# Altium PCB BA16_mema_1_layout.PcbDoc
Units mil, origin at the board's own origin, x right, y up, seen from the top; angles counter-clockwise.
Board outline 1653.54 x 2755.91 mil, 2 copper layers (Top Layer, Bottom Layer); 44 components, 23 nets, 138 pads, 0 vias.
Unrouted connection lines stored in the file: 87.
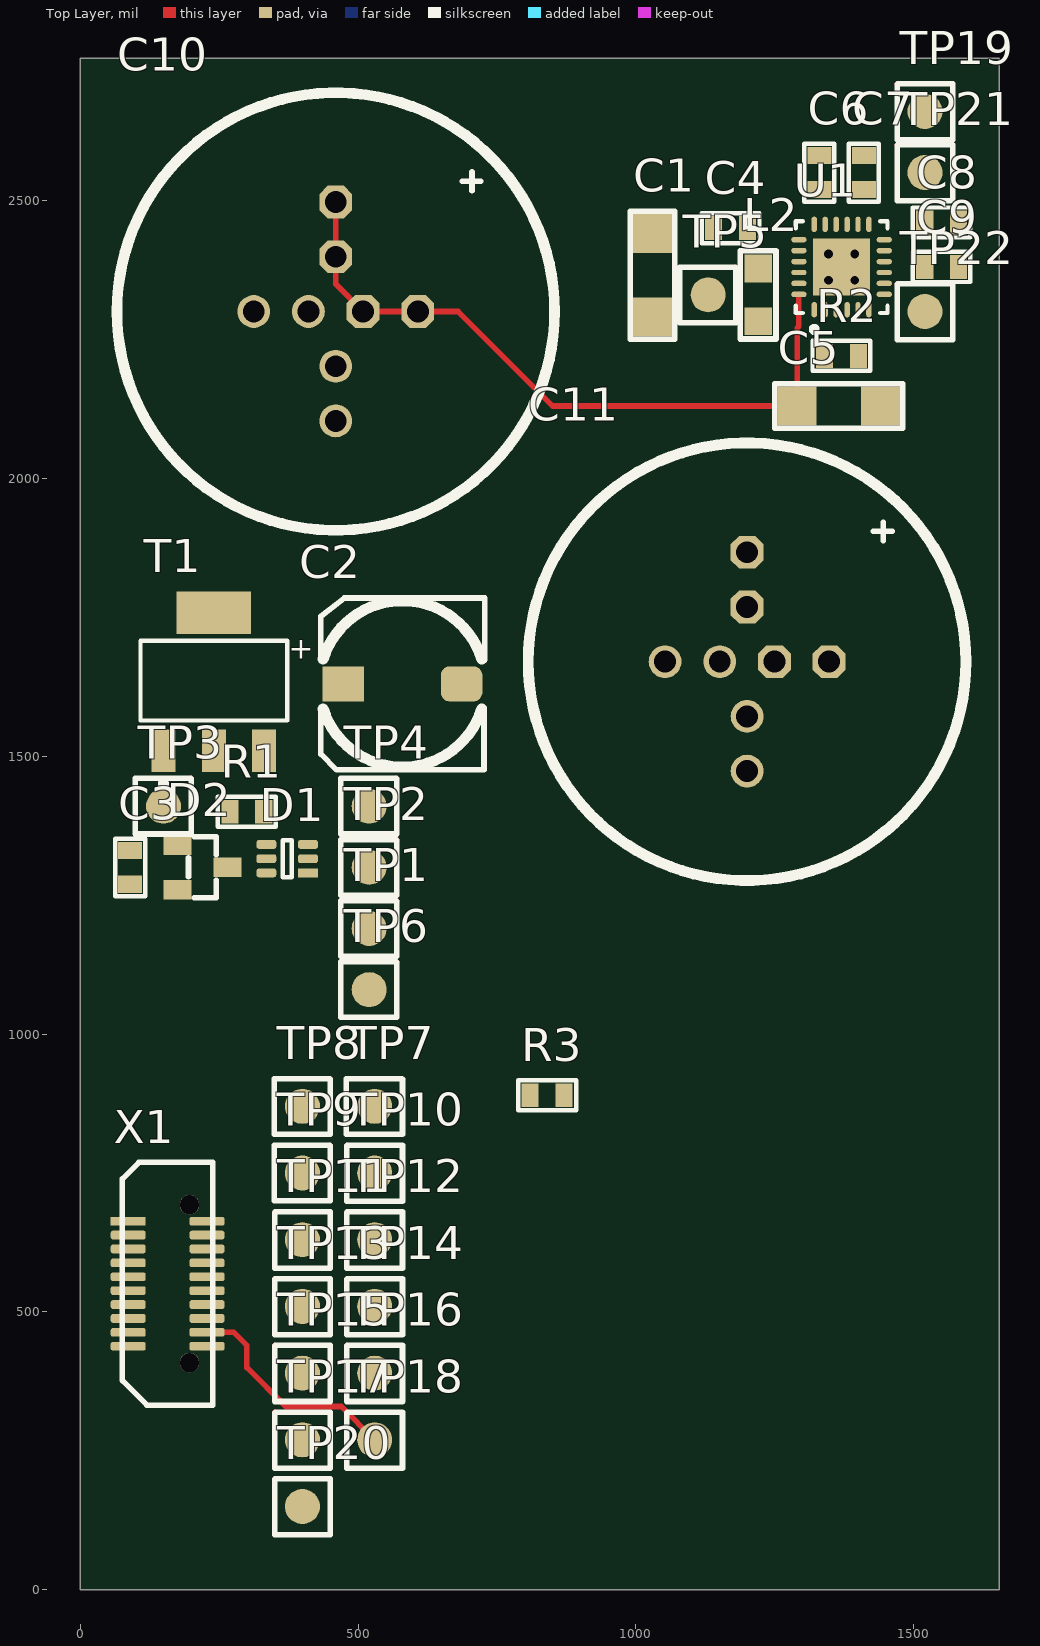
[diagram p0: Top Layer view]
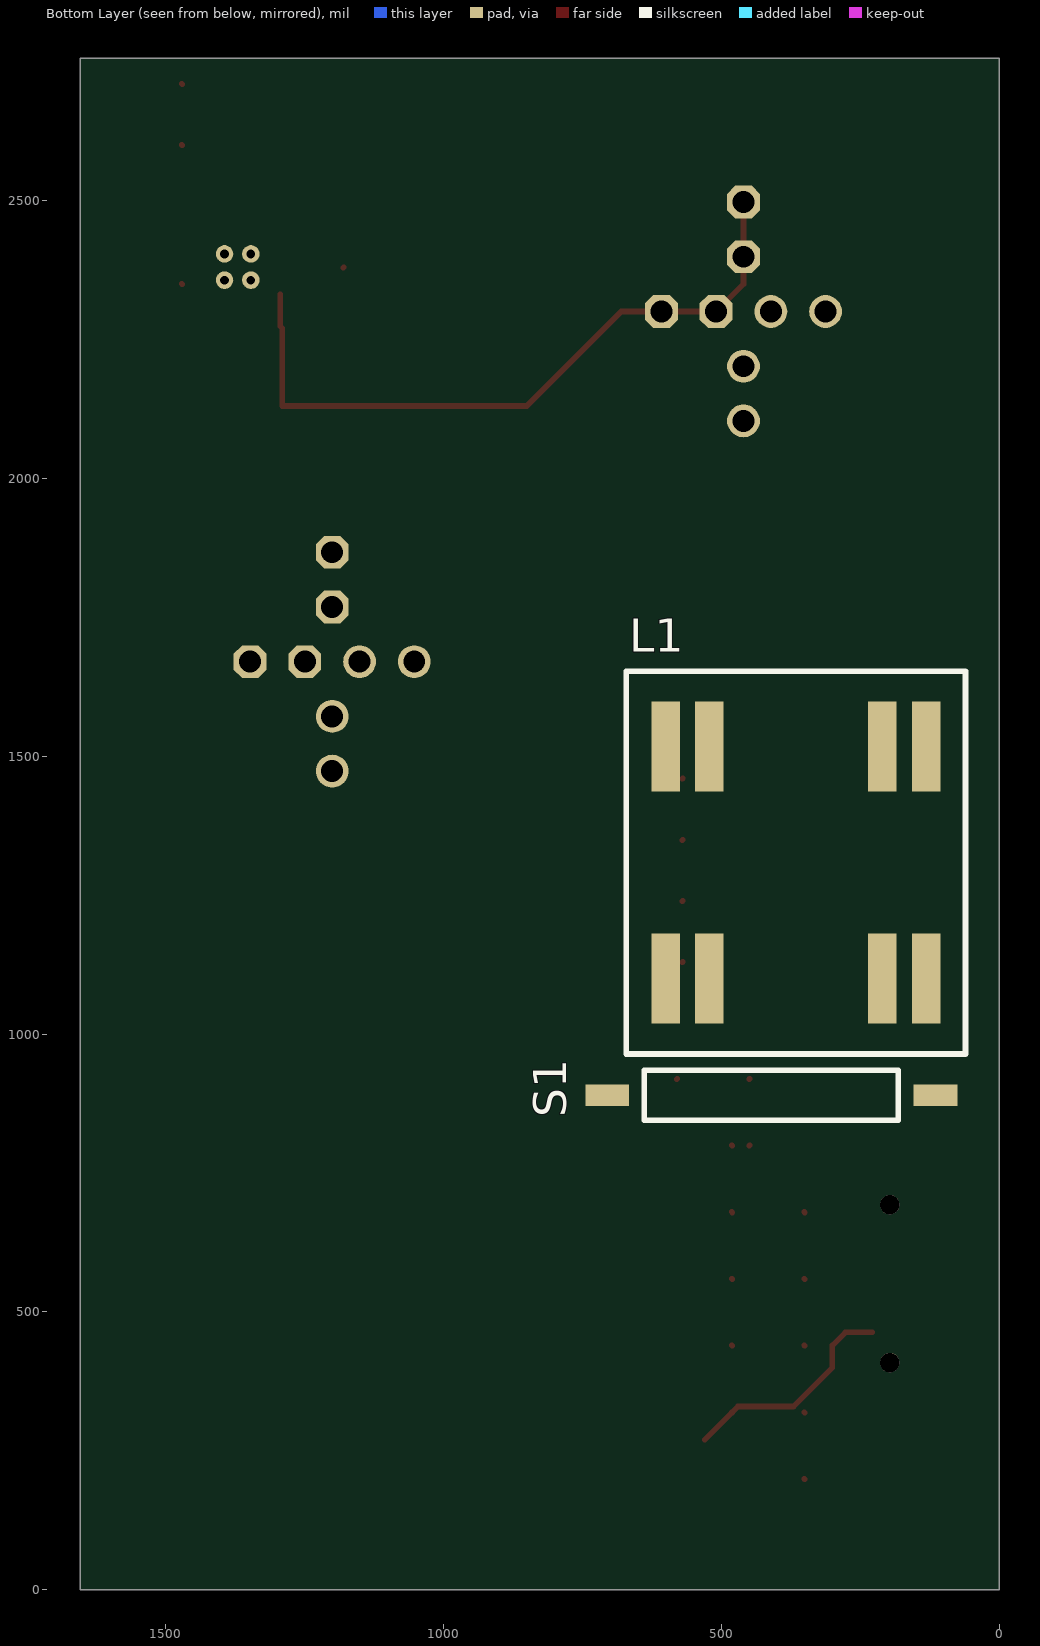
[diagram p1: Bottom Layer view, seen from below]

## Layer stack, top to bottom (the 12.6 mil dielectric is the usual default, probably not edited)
Top Solder: solder mask 0.4, Solder Resist, Dk 3.5
Top Layer: signal copper 1.4
Dielectric 1: dielectric 12.6, FR-4, Dk 4.8
Bottom Layer: signal copper 1.4
Bottom Solder: solder mask 0.4, Solder Resist, Dk 3.5

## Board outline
0,0 0,2755.91 1653.54,2755.91 1653.54,0

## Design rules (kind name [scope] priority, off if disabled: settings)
Clearance [All] p1: gap=10
PolygonConnect [All] p1: connectstyle=Relief reliefconductorwidth=10 reliefentries=4 polygonreliefangle="90 Angle" airgapwidth=10
RoutingVias [All] p1: holewidth=28 width=50 viastyle="Through Hole" minholewidth=28 minwidth=50 maxholewidth=28 maxwidth=50
SolderMaskExpansion [All] p1: expansion=4
Width [All] p1: maxlimit=10 minlimit=10 preferedwidth=10
30 further rules are at their usual default settings.

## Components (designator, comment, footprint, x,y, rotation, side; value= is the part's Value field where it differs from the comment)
C1 "Cap" "CHIP 1206" 1030,2290 r90 top
C2 "47uF 25V" "ELKO SMD-C 6.3x6.3" 580,1630 r0 top
C3 "1nF" "CHIP 0603" 90,1300 r90 top
C4 "Cap" "CHIP 0603" 1170,2450 r180 top
C5 "Cap" "CHIP 1206" 1290,2130 r0 top
C6 "Cap" "CHIP 0603" 1330,2550 r90 top
C7 "Cap" "CHIP 0603" 1410,2550 r90 top
C8 "Cap" "CHIP 0603" 1550,2460 r0 top
C9 "Cap" "CHIP 0603" 1550,2380 r0 top
C10 "3300uF 25V" C_RAD_flex 460,2300 r0 top
C11 "470uF 25V" C_RAD_flex 1200,1670 r0 top
D1 "HSMS-286P" "SOT-363 (SC-70)" 410,1290 r180 top
D2 "BAS16" SOT-23 220,1300 r270 top
L1 "X-Wicklung" PREMO_3115N_0238J_2 600,1100 r90 bottom
L2 "L" "CHIP 0805" 1220,2330 r270 top
R1 "1M" "CHIP 0603" 300,1400 r0 top
R2 "R" "CHIP 0603" 1370,2220 r0 top
R3 "10k 0603" "CHIP 0603" 840,890 r180 top
S1 "Reed Switch" MK16-C-2 410,890 r180 bottom
T1 "BSP149" SOT-223 150,1510 r0 top
TP1 "TP_SMD" "TP SMD" 520,1190 r0 top
TP2 "TP_SMD" "TP SMD" 520,1300 r0 top
TP3 "TP_SMD" "TP SMD" 150,1410 r0 top
TP4 "TP_SMD" "TP SMD" 520,1410 r0 top
TP5 "TP_SMD" "TP SMD" 1130,2330 r0 top
TP6 "TP_SMD" "TP SMD" 520,1080 r0 top
TP7 "TP_SMD" "TP SMD" 530,870 r0 top
TP8 "TP_SMD" "TP SMD" 400,870 r0 top
TP9 "TP_SMD" "TP SMD" 400,750 r0 top
TP10 "TP_SMD" "TP SMD" 530,750 r90 top
TP11 "TP_SMD" "TP SMD" 400,630 r90 top
TP12 "TP_SMD" "TP SMD" 530,630 r90 top
TP13 "TP_SMD" "TP SMD" 400,510 r90 top
TP14 "TP_SMD" "TP SMD" 530,510 r90 top
TP15 "TP_SMD" "TP SMD" 400,390 r90 top
TP16 "TP_SMD" "TP SMD" 530,390 r90 top
TP17 "TP_SMD" "TP SMD" 400,270 r90 top
TP18 "TP_SMD" "TP SMD" 530,270 r90 top
TP19 "TP_SMD" "TP SMD" 1520,2660 r90 top
TP20 "TP_SMD" "TP SMD" 400,150 r90 top
TP21 "TP_SMD" "TP SMD" 1520,2550 r90 top
TP22 "TP_SMD" "TP SMD" 1520,2300 r90 top
U1 "em8500" QFN-24 1370,2380 r90 top
X1 "LSS-110-01-F-DV-A-TR" "HEADER SMD 2x10 0.635mm" 86.61,663.39 r0 top locked

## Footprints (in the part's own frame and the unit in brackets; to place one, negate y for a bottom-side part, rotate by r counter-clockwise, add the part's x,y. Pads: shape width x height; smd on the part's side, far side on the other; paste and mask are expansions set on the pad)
C_RAD_flex [mm] "KONDENSATOR, AXIAL, Raster 5"
  oct 1.5x1.5 hole 1: 1(0,2.5) 1(0,5) 1(1.25,0) 1(3.75,0)
  round 1.5 hole 1: 2(-3.75,0) 2(-1.25,0) 2(0,-5) 2(0,-2.5)
  silkscreen extent -10,-10 10,10
"CHIP 0603" [mil] "Chip 0603 Body 1.6x0.8mm"
  rect 31x43 smd: 1(-30.5,0) 2(30.5,0)
  silkscreen extent -52,-27 52,27
"CHIP 0805" [mil] "Chip 0805 Body 2.0x1.2mm"
  rect 50x50 smd: 1(-47.5,0) 2(47.5,0)
  silkscreen extent -80,-32 80,32
"CHIP 1206" [mil] "Chip 1206 Body 3.2x1.6mm"
  rect 70x70 smd: 1(0,0) 2(150,0)
  silkscreen extent -40,-40 190,40
"ELKO SMD-C 6.3x6.3" [mm] "Elko SMD Size C 6.3x6.3mm H = 5.5mm"
  rect 1.9x1.6 smd: 1(-2.7,0)
  rrect50% 1.9x1.6 smd: 2(2.7,0)
  silkscreen extent -3.72,-3.93 3.75,3.93
"HEADER SMD 2x10 0.635mm" [mm] "LSS-110-01-F-DV-A"
  round 0.89 hole 0.89 unplated: 0(2.8,-6.465) 0(2.8,0.75)
  rect 1.6x0.4 smd: 1(0,0)
  rrect50% 1.6x0.4 smd: 2(3.6,0) 3(0,-0.635) 4(3.6,-0.635) 5(0,-1.27) 6(3.6,-1.27) 7(0,-1.905) 8(3.6,-1.905) 9(0,-2.54) 10(3.6,-2.54) 11(0,-3.175) 12(3.6,-3.175) 13(0,-3.81) 14(3.6,-3.81) 15(0,-4.445) 16(3.6,-4.445) 17(0,-5.08) 18(3.6,-5.08) 19(0,-5.715) 20(3.6,-5.715)
  silkscreen extent -0.27,-8.4 3.87,2.69
MK16-C-2 [mm] "REED SENSOR"
  rect 2x1 smd: 1(-7.5,0) 2(7.5,0)
  silkscreen extent -5.8,-1.15 5.8,1.15
PREMO_3115N_0238J_2 [mm] "3D Coil 15x15 2.38mH +/-5% @125kHz"
  rect 4.1x1.3 smd: 1(0,0) 2(0,-2) 3(0,-9.9) 4(0,-11.9) 5(10.6,-11.9) 6(10.6,-9.9) 7(10.6,-2) 8(10.6,0)
  silkscreen extent -3.45,-13.7 14.05,1.8
QFN-24 [mm] "24-Pin Plastic Quad Flat No-Lead 0.5 mm Pitch"
  oval 0.7x0.25 smd: 1(-1.95,1.25) 2(-1.95,0.75) 3(-1.95,0.25) 4(-1.95,-0.25) 5(-1.95,-0.75) 6(-1.95,-1.25) 13(1.95,-1.25) 14(1.95,-0.75) 15(1.95,-0.25) 16(1.95,0.25) 17(1.95,0.75) 18(1.95,1.25)
  oval 0.25x0.7 smd: 7(-1.25,-1.95) 8(-0.75,-1.95) 9(-0.25,-1.95) 10(0.25,-1.95) 11(0.75,-1.95) 12(1.25,-1.95) 19(1.25,1.95) 20(0.75,1.95) 21(0.25,1.95) 22(-0.25,1.95) 23(-0.75,1.95) 24(-1.25,1.95)
  round 0.8 hole 0.4: 25(-0.6,-0.6) 25(-0.6,0.6) 25(0.6,-0.6) 25(0.6,0.6)
  rect 2.6x2.6 smd: 25(0,0)
  silkscreen extent -2.97,-2.1 2.1,2.1, body extent -2.07,-2.07 2.07,2.07, height 1
SOT-23 [mil]
  rect 35x50 smd: 1(-40,-45) 2(40,-45) 3(0,45)
  silkscreen extent -55,-25 55,25
SOT-223 [mm] "SOT-223/SC-73; 4 Leads; Body 6.7 x 7.3 mm, inc. leads (LxW max)"
  rect 1.1x1.95 smd: 1(0,0) 2(2.3,0) 3(4.6,0)
  rect 3.4x1.95 smd: 4(2.3,6.3)
  silkscreen extent -1.05,-1.65 5.65,5.02
"SOT-363 (SC-70)" [mm]
  rect 0.9x0.4 smd: 1(0,0)
  rrect50% 0.9x0.4 smd: 2(0,-0.65) 3(0,-1.3) 4(1.9,-1.3) 5(1.9,-0.65) 6(1.9,0)
  silkscreen extent 0.75,-1.5 1.15,0.2
"TP SMD" [mm] "Testpoint SMD"
  round 1.6 smd: 1(0,0)
  Top Layer lines w0.254: 1.245,1.27 1.27,1.245
  silkscreen extent -1.3,-1.27 1.27,1.27

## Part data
C1 C4 C5 C6 C7 C8 C9: library part C, "Capacitor"
C2 C10 C11: library part "C POL", "Capasitor Polarisiert"
C3: library part "C 50V", "Capacitor 50V"
D1: "Diode Schottky Quadro"
D2: library part D, "Diode"
L1: library part "PREMO 3015 0238J 2", "Inductor"
L2: "Ind"
R1 R3: library part R, "Resistor"
R2: "Resistor"
S1: library part "SWITCH MICRO NO", "Switch Micro Normal Open"
T1: "MOSFET N-Kanal"
TP1 TP2 TP3 TP4 TP5 TP6 TP7 TP8 TP9 TP10 TP11 TP12 TP13 TP14 TP15 TP16 TP17 TP18 TP19 TP20 TP21 TP22: "Testpoint SMD"
X1: library part "HDR 20 POL ABW", "Header 100 mil 20 Pol"

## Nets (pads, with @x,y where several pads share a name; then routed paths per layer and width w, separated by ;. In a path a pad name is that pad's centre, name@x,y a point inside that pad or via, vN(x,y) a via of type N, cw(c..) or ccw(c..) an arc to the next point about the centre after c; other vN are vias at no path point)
BAT_LOW: TP13.1 U1.18 X1.12
EM_CS: TP9.1 U1.7 X1.7
GND: C1.2 C2.2 C3.1 C4.2 C5.2 C6.2 C7.2 C8.2 C9.2 C10.2 C11.2 D1.1 D1.6 D2.2 R2.2 TP7.1 U1.20 U1.21 X1.2
HRV_LOW: TP11.1 U1.17 X1.10
MCU_MISO: TP14.1 U1.5 X1.13
MCU_MOSI: TP12.1 U1.4 X1.11
MCU_SCLK: TP16.1 U1.6 X1.15
NetC3_2: C3.2 D2.1 R1.1 T1.1 TP3.1
NetD1_2: D1.2 L1.8 TP1.1
NetD1_3: D1.3 D1.4 R1.2 T1.3 TP2.1
NetD1_5: D1.5 L1.4 TP6.1
NetL2_1: L2.1 TP5.1 U1.22
NetR3_2: R3.2 S1.1
REED_SWITCH: R3.1 TP20.1 X1.20
VAUX_VCC0: C9.1 TP22.1 U1.12
VAUX_VCC1: C8.1 TP21.1 U1.13
VAUX_VCC2: C7.1 TP19.1 U1.14
VCC: C1.1 C2.1 L2.2 T1.2 TP4.1 U1.23
VCC_LTS: C5.1 C10.1 TP18.1 U1.24 X1.18
VCC_STS: C11.1 TP17.1 U1.1 X1.16
VREG: C4.1 TP15.1 U1.19 X1.14
VSUP: C6.1 S1.2 TP8.1 U1.16 X1.1
WAKE_UP: R2.1 TP10.1 U1.2 X1.8
pads on no net: D2.3 L1.1 L1.2 L1.3 L1.5 L1.6 L1.7 T1.4 U1.3 U1.8 U1.9 U1.10 U1.11 U1.15 U1.25 X1.0 X1.3 X1.4 X1.5 X1.6 X1.9 X1.17 X1.19
copper on no net: | length 1675.8
  Top Layer w10: 228.35,463.39 276.61,463.39 300,440 300,400 370,330 470,330 530,270 ; 460,2496.85 460,2398.43 460,2349.21 509.21,2300 607.64,2300 680,2300 850,2130 1290,2130 1290,2270 1293.23,2273.23 1293.23,2330.79

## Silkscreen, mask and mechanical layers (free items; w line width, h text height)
Mechanical 1:
  lines w10: 0,332.68 1653.54,332.68 ; 0,769.68 1653.54,769.68 ; 0,1259.84 1653.54,1259.84 ; 75.2,0 75.2,2755.91
  lines w78.74: 0,0 0,2755.91 1653.54,2755.91 1653.54,0 0,0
